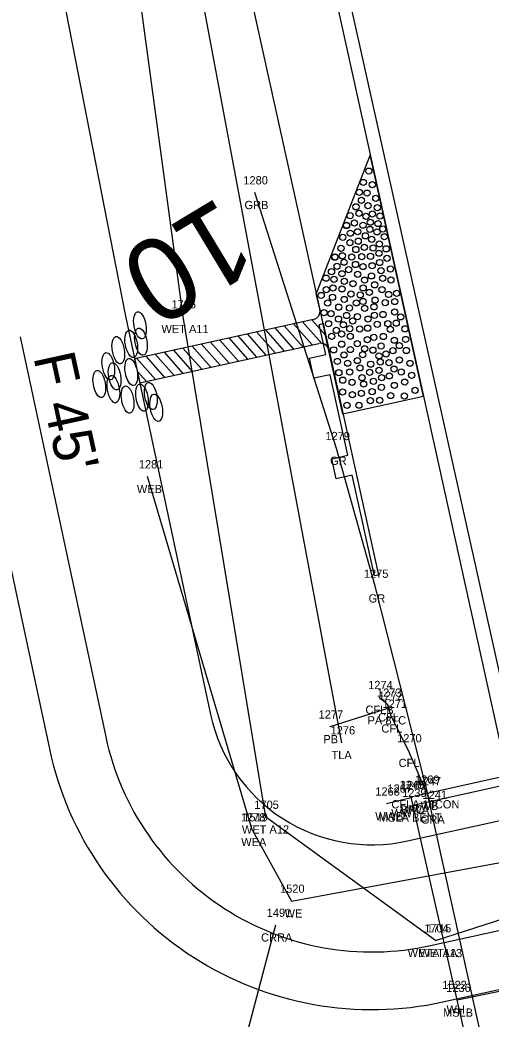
# Model space of a CAD drawing. Extents: x 2521558 to 2525396, y 882711 to 887632.
# Drawn here: x 2523710.8 to 2523767.9, y 885124.5 to 885245.8 of the extents above; entities that cross this region are included whole.
import ezdxf

# ---------------------------------------------------------------- set-up
doc = ezdxf.new("R2010")
doc.units = 0
for name, color, linetype in [('RD_EV_JurisArea', 7, 'Continuous'), ('RD_EX_BldgApp', 7, 'Continuous'), ('RD_EX_BldgApp_txCode', 7, 'Continuous'), ('RD_EX_Bridge', 7, 'Continuous'), ('RD_EX_Bridge_txCode', 7, 'Continuous'), ('RD_EX_Conc', 7, 'Continuous'), ('RD_EX_Conc_txCode', 7, 'Continuous'), ('RD_EX_DR_Pipe', 7, 'Continuous'), ('RD_EX_DR_Pipe_txCode', 7, 'Continuous'), ('RD_EX_GuardRail', 7, 'Continuous'), ('RD_EX_GuardRail_txCode', 7, 'Continuous'), ('RD_EX_H2O', 7, 'Continuous'), ('RD_EX_H2O_txCode', 7, 'Continuous'), ('RD_EX_H2O_WetLd_txCode', 7, 'Continuous'), ('RD_EX_Misc', 7, 'Continuous'), ('RD_EX_Misc_txCode', 7, 'Continuous'), ('RD_EX_Road', 7, 'Continuous'), ('RD_EX_VEG', 7, 'Continuous'), ('RD_EX_VEG_txCode', 7, 'Continuous'), ('RD_HC_TX_Sta50', 7, 'Continuous'), ('RD_PD_BCA', 7, 'Continuous'), ('RD_PD_Bridge', 7, 'Continuous'), ('RD_PD_CstnLmt', 7, 'Continuous'), ('RD_PD_DR_ErosCtrl', 7, 'Continuous'), ('RD_PD_Final_TrvlWay', 7, 'Continuous'), ('RD_PD_GR', 7, 'Continuous'), ('RD_PD_PaveShd', 7, 'Continuous'), ('RD_SMD_Locator', 7, 'Continuous')]:
    doc.layers.add(name, color=color, linetype=linetype)

# ---------------------------------------------------------------- blocks, each defined once
blk = doc.blocks.new('TBC1')
at = {"layer": 'RD_PD_GR'}
blk.add_lwpolyline([(12.5, 2.5), (15, 2.5), (15, 0.49), (25, 0.49), (25, 2.5), (27.5, 2.5), (27.5, 0.49), (31.25, 0.49), (31.25, 0), (0, 0), (0, 0.49), (12.5, 0.49)], close=True, dxfattribs=at)

msp = doc.modelspace()

# ---------------------------------------------------------------- linework, layer by layer
at = {"layer": 'RD_EV_JurisArea'}
for points in [[(2523761.17, 885134.03), (2523740.58, 885149.03), (2523730.55, 885209.77), (2523710.6, 885357.47), (2523698.09, 885411.19), (2523674.93, 885498.62), (2523657.6, 885564.24), (2523640.82, 885610.87), (2523583.66, 885726.91), (2523539.21, 885693.17), (2523494.42, 885646.98)], [(2523761.17, 885134.03), (2523808.21, 885149.21), (2523821.91, 885178.64), (2523802.85, 885236.55), (2523777.81, 885305.56), (2523748.2, 885444.32), (2523730.68, 885516.88), (2523708.64, 885617.3), (2523698.71, 885662.02), (2523727.83, 885665.82), (2523757.3, 885671.75)]]:
    msp.add_lwpolyline(points, dxfattribs=at)
at = {"layer": 'RD_EX_BldgApp'}
msp.add_lwpolyline([(2523776.68, 885077.92), (2523768.27, 885115.31), (2523760.2, 885151.9)], dxfattribs=at)
at = {"layer": 'RD_EX_Bridge'}
for points in [[(2523774.91, 885077.6), (2523821.2, 885087.83), (2523805.06, 885161.89), (2523758.15, 885151.44), (2523774.91, 885077.6)], [(2523758.38, 885151.39), (2523756.7, 885150.99), (2523755.23, 885150.64)]]:
    msp.add_lwpolyline(points, dxfattribs=at)
at = {"layer": 'RD_EX_Conc'}
msp.add_lwpolyline([(2523760.04, 885152.08), (2523757.9, 885157.1), (2523755.8, 885161.28), (2523755.4, 885162.64), (2523754.34, 885163.56)], dxfattribs=at)
at = {"layer": 'RD_EX_DR_Pipe'}
msp.add_line((2523755.61, 885162.27), (2523748.33, 885159.99), dxfattribs=at)
at = {"layer": 'RD_EX_GuardRail'}
for p, q in [((2523749.16, 885193.78), (2523739.25, 885224.82)), ((2523753.83, 885177.07), (2523749.16, 885193.78)), ((2523760.65, 885150.24), (2523753.83, 885177.07))]:
    msp.add_line(p, q, dxfattribs=at)
at = {"layer": 'RD_EX_H2O'}
msp.add_line((2523738.91, 885147.5), (2523726.24, 885190.35), dxfattribs=at)
for points in [[(2523738.91, 885147.5), (2523743.69, 885138.84), (2523816.36, 885152.29), (2523822.43, 885163.3), (2523826.93, 885206.61)], [(2523741.75, 885135.92), (2523732.18, 885099.57), (2523664.9, 885060.26), (2523614.86, 885022.02), (2523558.95, 884972.63), (2523560.62, 884942.42), (2523490.01, 884911.76)]]:
    msp.add_lwpolyline(points, dxfattribs=at)
at = {"layer": 'RD_EX_Misc'}
for p, q in [((2523758.45, 885150.47), (2523805.66, 885161.06)), ((2523810.71, 885136.57), (2523763.83, 885126.8))]:
    msp.add_line(p, q, dxfattribs=at)
at = {"layer": 'RD_EX_Road'}
msp.add_line((2523771.58, 885154.56), (2523750.32, 885250.18), dxfattribs=at)
at = {"layer": 'RD_EX_VEG'}
msp.add_lwpolyline([(2523749.81, 885158.06), (2523732.86, 885248.57), (2523691.62, 885438.95), (2523639.52, 885601.04)], dxfattribs=at)
at = {"layer": 'RD_PD_BCA'}
msp.add_line((2523703.95, 885205.86), (2523714.34, 885157.3), dxfattribs=at)
msp.add_lwpolyline([(2523762.05, 885126.6), (2523810.84, 885137.34)], dxfattribs=at)
msp.add_arc((2523753.45, 885165.66), 40, 192.0677, 282.4185, dxfattribs=at)
at = {"layer": 'RD_PD_CstnLmt'}
for p, q in [((2523704.35, 885308.21), (2523723.51, 885210.04)), ((2523723.51, 885210.04), (2523733.89, 885161.48))]:
    msp.add_line(p, q, dxfattribs=at)
msp.add_lwpolyline([(2523757.75, 885146.13), (2523806.54, 885156.87)], dxfattribs=at)
msp.add_arc((2523753.45, 885165.66), 20, 192.0677, 282.4185, dxfattribs=at)
at = {"layer": 'RD_PD_DR_ErosCtrl'}
msp.add_line((2523710.8, 885207.32), (2523721.18, 885158.76), dxfattribs=at)
msp.add_lwpolyline([(2523760.55, 885133.43), (2523809.33, 885144.17)], dxfattribs=at)
msp.add_arc((2523753.45, 885165.66), 33, 192.0677, 282.4185, dxfattribs=at)
at = {"layer": 'RD_PD_Final_TrvlWay'}
msp.add_line((2523696.8, 885485.75), (2524014, 884045.26), dxfattribs=at)
at = {"layer": 'RD_PD_GR'}
msp.add_line((2523747.52, 885208.93), (2523699.13, 885428.66), dxfattribs=at)
at = {"layer": 'RD_PD_PaveShd'}
for p, q in [((2523753.25, 885229.39), (2523746.71, 885212.59)), ((2523759.7, 885200.09), (2523753.25, 885229.39)), ((2523747.36, 885209.66), (2523746.71, 885212.59)), ((2523746.38, 885209.44), (2523724.66, 885204.65)), ((2523747.37, 885206.53), (2523745.05, 885209.15)), ((2523747.82, 885207.53), (2523746.17, 885209.4)), ((2523748, 885206.73), (2523747.36, 885209.66)), ((2523741.74, 885205.35), (2523739.47, 885207.92)), ((2523742.86, 885205.6), (2523740.59, 885208.17)), ((2523743.98, 885205.84), (2523741.7, 885208.41)), ((2523745.09, 885206.09), (2523742.82, 885208.66)), ((2523746.21, 885206.34), (2523743.94, 885208.91)), ((2523736.16, 885204.12), (2523733.88, 885206.69)), ((2523737.27, 885204.36), (2523735, 885206.93)), ((2523738.39, 885204.61), (2523736.12, 885207.18)), ((2523739.51, 885204.86), (2523737.23, 885207.43)), ((2523740.63, 885205.1), (2523738.35, 885207.67)), ((2523748, 885206.73), (2523749.94, 885197.94)), ((2523749.94, 885197.94), (2523748, 885206.73)), ((2523725.29, 885201.72), (2523747.02, 885206.51)), ((2523730.57, 885202.88), (2523728.3, 885205.45)), ((2523731.69, 885203.13), (2523729.42, 885205.7)), ((2523732.81, 885203.38), (2523730.53, 885205.95)), ((2523733.92, 885203.62), (2523731.65, 885206.19)), ((2523735.04, 885203.87), (2523732.77, 885206.44)), ((2523724.66, 885204.65), (2523725.29, 885201.72)), ((2523727.22, 885202.14), (2523724.95, 885204.71)), ((2523728.34, 885202.39), (2523726.06, 885204.96)), ((2523729.46, 885202.64), (2523727.18, 885205.21)), ((2523726.1, 885201.9), (2523724.98, 885203.17)), ((2523759.7, 885200.09), (2523749.94, 885197.94))]:
    msp.add_line(p, q, dxfattribs=at)
for centre in [(2523753.08, 885227.43), (2523753.08, 885227.43), (2523752.41, 885226.06), (2523752.41, 885226.06), (2523753.51, 885225.78), (2523753.51, 885225.78), (2523751.93, 885224.85), (2523751.93, 885224.85), (2523752.87, 885224.76), (2523752.87, 885224.76), (2523752.18, 885223.88), (2523752.18, 885223.88), (2523752.97, 885223.25), (2523752.97, 885223.25), (2523753.92, 885224.14), (2523753.92, 885224.14), (2523750.81, 885222.03), (2523750.81, 885222.03), (2523751.52, 885223.1), (2523751.89, 885222.31), (2523751.89, 885222.31), (2523753.5, 885222.22), (2523753.5, 885222.22), (2523754.11, 885222.99), (2523754.11, 885222.99), (2523754.42, 885221.99), (2523754.42, 885221.99), (2523750.37, 885220.83), (2523750.38, 885220.87), (2523751.33, 885221.14), (2523751.33, 885221.14), (2523752.36, 885220.87), (2523752.36, 885220.87), (2523752.73, 885221.95), (2523752.73, 885221.95), (2523753.25, 885221.23), (2523753.25, 885221.23), (2523754.19, 885221.07), (2523754.19, 885221.07), (2523750.84, 885219.9), (2523750.84, 885219.9), (2523751.73, 885220.07), (2523751.73, 885220.07), (2523752.67, 885219.58), (2523752.67, 885219.58), (2523753.2, 885220.35), (2523753.2, 885220.35), (2523754.06, 885220.06), (2523754.06, 885220.06), (2523754.77, 885220.41), (2523754.77, 885220.41), (2523749.92, 885219.4), (2523749.92, 885219.4), (2523750.78, 885218.75), (2523750.78, 885218.75), (2523751.79, 885218.93), (2523751.79, 885218.93), (2523753.43, 885219.15), (2523753.43, 885219.15), (2523754.34, 885218.6), (2523754.34, 885218.6), (2523754.95, 885219.46), (2523754.95, 885219.46), (2523749.7, 885218.06), (2523749.7, 885218.06), (2523749.87, 885217.15), (2523749.87, 885217.15), (2523751.5, 885217.92), (2523751.5, 885217.92), (2523752.53, 885218.18), (2523752.53, 885218.18), (2523753.6, 885218.1), (2523753.6, 885218.1), (2523754.3, 885217.47), (2523754.3, 885217.47), (2523755.18, 885218), (2523755.18, 885218), (2523748.95, 885216.99), (2523748.96, 885217), (2523750.08, 885216.38), (2523750.08, 885216.38), (2523751.01, 885217), (2523751.01, 885217), (2523751.46, 885216.1), (2523751.46, 885216.1), (2523752.22, 885217.06), (2523752.22, 885217.06), (2523753.28, 885217.1), (2523753.28, 885217.1), (2523753.48, 885215.94), (2523753.48, 885215.94), (2523754.38, 885216.34), (2523754.38, 885216.34), (2523755.27, 885216.85), (2523755.27, 885216.85), (2523748.55, 885215.24), (2523748.55, 885215.24), (2523749.23, 885215.87), (2523749.23, 885215.87), (2523749.82, 885214.97), (2523749.82, 885214.97), (2523750.64, 885215.48), (2523750.64, 885215.48), (2523751.73, 885214.91), (2523751.73, 885214.91), (2523752.37, 885215.85), (2523752.37, 885215.85), (2523753.4, 885214.72), (2523753.4, 885214.72), (2523754.56, 885215.35), (2523754.56, 885215.35), (2523755.7, 885215.56), (2523755.7, 885215.56), (2523747.88, 885214.44), (2523747.88, 885214.44), (2523748.85, 885214.3), (2523748.85, 885214.3), (2523750.1, 885214.05), (2523750.1, 885214.05), (2523751.15, 885213.76), (2523751.15, 885213.76), (2523752.56, 885214.2), (2523752.56, 885214.2), (2523753.78, 885213.63), (2523753.78, 885213.63), (2523754.76, 885214.43), (2523754.76, 885214.43), (2523755.75, 885214.21), (2523755.75, 885214.21), (2523747.3, 885212.34), (2523747.3, 885212.34), (2523747.3, 885212.34), (2523747.91, 885213.04), (2523747.91, 885213.04), (2523748.73, 885213.24), (2523748.73, 885213.24), (2523749.82, 885213.14), (2523749.82, 885213.14), (2523750.91, 885212.52), (2523750.91, 885212.52), (2523752.03, 885212.41), (2523752.03, 885212.41), (2523752.39, 885213.26), (2523752.39, 885213.26), (2523753.14, 885212.71), (2523753.14, 885212.71), (2523754.68, 885213.04), (2523754.68, 885213.04), (2523755.48, 885212.46), (2523755.48, 885212.46), (2523756.44, 885212.6), (2523756.44, 885212.6), (2523748.09, 885211.43), (2523748.09, 885211.43), (2523748.67, 885212.12), (2523748.67, 885212.12), (2523750.09, 885211.86), (2523750.09, 885211.86), (2523751.57, 885211.44), (2523751.57, 885211.44), (2523752.37, 885211.61), (2523752.37, 885211.61), (2523753.84, 885211.77), (2523753.84, 885211.77), (2523755.06, 885211.47), (2523755.06, 885211.47), (2523756.21, 885211.6), (2523756.21, 885211.6), (2523747.64, 885210.26), (2523747.64, 885210.26), (2523748.49, 885210.14), (2523748.49, 885210.14), (2523749.43, 885210.92), (2523749.43, 885210.92), (2523750.38, 885209.91), (2523750.38, 885209.91), (2523750.73, 885210.81), (2523750.73, 885210.81), (2523752.58, 885210.78), (2523752.58, 885210.78), (2523753.71, 885210.96), (2523753.71, 885210.96), (2523753.76, 885209.93), (2523753.76, 885209.93), (2523754.8, 885210.03), (2523754.8, 885210.03), (2523756.2, 885210.33), (2523756.2, 885210.33), (2523748.19, 885208.9), (2523748.19, 885208.9), (2523749.4, 885209.47), (2523749.4, 885209.47), (2523749.98, 885208.78), (2523749.98, 885208.78), (2523751.11, 885209.24), (2523751.11, 885209.24), (2523751.7, 885209.77), (2523751.7, 885209.77), (2523752.97, 885209.47), (2523752.97, 885209.47), (2523754.09, 885208.84), (2523754.09, 885208.84), (2523755.38, 885208.92), (2523755.38, 885208.92), (2523756.4, 885208.98), (2523756.4, 885208.98), (2523756.94, 885209.74), (2523749.13, 885208.1), (2523749.13, 885208.1), (2523749.78, 885207.67), (2523749.78, 885207.67), (2523750.77, 885208.31), (2523750.77, 885208.31), (2523751.97, 885208.26), (2523751.97, 885208.26), (2523752.93, 885208.37), (2523752.93, 885208.37), (2523755.68, 885208.23), (2523755.68, 885208.23), (2523757.45, 885208.29), (2523757.45, 885208.29), (2523748.58, 885207.38), (2523748.58, 885207.38), (2523749.78, 885206.43), (2523749.78, 885206.43), (2523750.82, 885207.38), (2523750.82, 885207.38), (2523751.67, 885206.49), (2523751.67, 885206.49), (2523752.9, 885206.97), (2523752.9, 885206.97), (2523753.68, 885207.26), (2523753.68, 885207.26), (2523754.84, 885207.36), (2523754.84, 885207.36), (2523756.16, 885206.91), (2523756.16, 885206.91), (2523756.77, 885206.26), (2523756.77, 885206.26), (2523757.54, 885207), (2523757.54, 885207), (2523748.82, 885205.74), (2523748.82, 885205.74), (2523750.07, 885205.13), (2523750.07, 885205.13), (2523750.84, 885205.78), (2523750.84, 885205.78), (2523752.34, 885205.15), (2523752.34, 885205.15), (2523752.58, 885205.87), (2523752.58, 885205.87), (2523753.57, 885205.7), (2523753.57, 885205.7), (2523754.3, 885205.01), (2523754.3, 885205.01), (2523754.57, 885206.2), (2523754.57, 885206.2), (2523755.16, 885205.23), (2523755.16, 885205.23), (2523755.99, 885205.63), (2523755.99, 885205.63), (2523757.63, 885205.66), (2523757.63, 885205.66), (2523749.26, 885204.33), (2523749.26, 885204.33), (2523750.51, 885204.12), (2523750.51, 885204.12), (2523751.68, 885204.44), (2523751.68, 885204.44), (2523753.31, 885204), (2523753.31, 885204), (2523754.46, 885204.26), (2523755.52, 885204.19), (2523755.52, 885204.19), (2523756.78, 885204.5), (2523756.78, 885204.5), (2523758.07, 885204.09), (2523758.07, 885204.09), (2523749.44, 885202.96), (2523749.44, 885202.96), (2523750.76, 885203.04), (2523750.76, 885203.04), (2523751.99, 885203.55), (2523751.99, 885203.55), (2523753.17, 885203), (2523753.17, 885203), (2523754.32, 885203.25), (2523754.32, 885203.25), (2523755.57, 885202.58), (2523755.57, 885202.58), (2523756.14, 885203.4), (2523756.14, 885203.4), (2523757, 885203.06), (2523757, 885203.06), (2523758.26, 885202.64), (2523758.26, 885202.64), (2523749.92, 885202.06), (2523749.92, 885202.06), (2523751.05, 885201.79), (2523751.05, 885201.79), (2523752.24, 885202.37), (2523752.24, 885202.37), (2523752.44, 885201.58), (2523752.44, 885201.58), (2523753.64, 885201.92), (2523753.64, 885201.92), (2523754.62, 885202.37), (2523754.62, 885202.37), (2523756.17, 885201.42), (2523756.17, 885201.42), (2523757.43, 885201.82), (2523757.43, 885201.82), (2523749.89, 885200.63), (2523749.89, 885200.63), (2523751.08, 885200.3), (2523751.08, 885200.3), (2523752.18, 885200.46), (2523752.18, 885200.46), (2523753.48, 885200.66), (2523753.48, 885200.66), (2523754.61, 885201.18), (2523754.61, 885201.18), (2523755.73, 885200.19), (2523755.73, 885200.19), (2523758.69, 885200.82), (2523758.69, 885200.82), (2523750.43, 885199), (2523750.43, 885199), (2523750.43, 885199), (2523751.87, 885199.02), (2523751.87, 885199.02), (2523753.25, 885199.58), (2523753.25, 885199.58), (2523754.4, 885199.62), (2523754.4, 885199.62), (2523757.38, 885200.14), (2523757.38, 885200.14)]:
    msp.add_circle(centre, 0.375, dxfattribs=at)
for centre, start, end in [((2523746.16, 885210.42), 282.4481, 12.4185), ((2523747.24, 885205.54), 12.4185, 102.4481)]:
    msp.add_arc(centre, 1, start, end, dxfattribs=at)
for centre in [(2523725.32, 885208.71), (2523724.26, 885206.47), (2523724.26, 885206.47), (2523725.44, 885206.73), (2523722.69, 885205.7), (2523722.69, 885205.7), (2523721.48, 885203.75), (2523721.48, 885203.75), (2523722.25, 885202.53), (2523722.25, 885202.53), (2523724.26, 885203.06), (2523724.26, 885203.06), (2523720.39, 885201.6), (2523720.39, 885201.6), (2523722.1, 885200.97), (2523722.1, 885200.97), (2523726.64, 885200.14), (2523726.64, 885200.14), (2523723.82, 885199.71), (2523723.82, 885199.71), (2523725.57, 885199.94), (2523725.57, 885199.94), (2523727.29, 885198.71), (2523727.29, 885198.71)]:
    msp.add_ellipse(centre, major_axis=(-0.29, 1.65), ratio=0.429445, dxfattribs=at)
at = {"layer": 'RD_SMD_Locator'}
for centre in [(2523739.25, 885224.82), (2523732.01, 885210.1), (2523749.16, 885193.78), (2523726.24, 885190.35), (2523753.83, 885177.07), (2523754.34, 885163.56), (2523755.4, 885162.64), (2523755.61, 885162.27), (2523755.8, 885161.28), (2523748.33, 885159.99), (2523749.81, 885158.06), (2523757.9, 885157.1), (2523760.04, 885152.08), (2523756.7, 885150.99), (2523758.15, 885151.44), (2523758.38, 885151.39), (2523760.2, 885151.9), (2523755.23, 885150.64), (2523758.45, 885150.47), (2523760.65, 885150.24), (2523740.58, 885149.03), (2523738.91, 885147.5), (2523738.91, 885147.5), (2523743.69, 885138.84), (2523741.75, 885135.92), (2523761.17, 885134.03), (2523761.17, 885134.03), (2523763.32, 885127.16), (2523763.83, 885126.8)]:
    msp.add_circle(centre, 0.001, dxfattribs=at)

# ---------------------------------------------------------------- block references
at = {"layer": 'RD_PD_Bridge', "rotation": 102.41848259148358}
msp.add_blockref('TBC1', (2523754.24, 885178.41), dxfattribs=at)

# ---------------------------------------------------------------- texts
at = {"layer": 'RD_EX_BldgApp_txCode'}
for s, p in [('1247', (2523758.86, 885152.9)), ('WB', (2523759.36, 885149.9)), ('1522', (2523761.98, 885128.16)), ('WH', (2523762.5, 885125.16))]:
    msp.add_text(s, height=1, dxfattribs=at).set_placement(p)
at = {"layer": 'RD_EX_Bridge_txCode'}
for s, p in [('1245', (2523756.8, 885152.44)), ('1266', (2523756.98, 885152.39)), ('1268', (2523753.86, 885151.64)), ('1267', (2523755.33, 885151.99)), ('WWB', (2523753.85, 885148.64)), ('WW', (2523755.8, 885148.99)), ('WWA', (2523756.98, 885149.39)), ('BRC', (2523756.89, 885149.44))]:
    msp.add_text(s, height=1, dxfattribs=at).set_placement(p)
at = {"layer": 'RD_EX_Conc_txCode'}
for s, p in [('1274', (2523753, 885164.56)), ('1273', (2523754.06, 885163.64)), ('1271', (2523754.74, 885162.28)), ('CFLB', (2523752.67, 885161.56)), ('CFL', (2523754.2, 885160.64)), ('CFL', (2523754.6, 885159.28)), ('1270', (2523756.51, 885158.1)), ('CFL', (2523756.69, 885155.1)), ('1269', (2523758.67, 885153.08)), ('CFLA 18CON', (2523755.81, 885150.08))]:
    msp.add_text(s, height=1, dxfattribs=at).set_placement(p)
at = {"layer": 'RD_EX_DR_Pipe_txCode'}
for s, p in [('1272', (2523754.27, 885163.27)), ('1277', (2523746.99, 885160.99)), ('PA 8TC', (2523752.92, 885160.27)), ('PB', (2523747.56, 885157.99))]:
    msp.add_text(s, height=1, dxfattribs=at).set_placement(p)
at = {"layer": 'RD_EX_GuardRail_txCode'}
for s, p in [('1280', (2523737.86, 885225.82)), ('GRB', (2523738, 885222.82)), ('1279', (2523747.81, 885194.78)), ('GR', (2523748.38, 885191.78)), ('1275', (2523752.48, 885178.07)), ('GR', (2523753.05, 885175.07)), ('1241', (2523759.59, 885151.24)), ('GRA', (2523759.38, 885148.24))]:
    msp.add_text(s, height=1, dxfattribs=at).set_placement(p)
at = {"layer": 'RD_EX_H2O_txCode'}
for s, p in [('1281', (2523725.18, 885191.35)), ('WEB', (2523724.95, 885188.35)), ('1278', (2523737.56, 885148.5)), ('1519', (2523737.85, 885148.5)), ('WEA', (2523737.6, 885145.5)), ('WEA', (2523737.6, 885145.5)), ('1520', (2523742.31, 885139.84)), ('1491', (2523740.69, 885136.92)), ('WE', (2523742.86, 885136.84)), ('CRRA', (2523740.01, 885133.92))]:
    msp.add_text(s, height=1, dxfattribs=at).set_placement(p)
at = {"layer": 'RD_EX_H2O_WetLd_txCode'}
for s, p in [('1706', (2523729.14, 885210.77)), ('WET A11', (2523727.93, 885207.77)), ('1705', (2523739.19, 885150.03)), ('WET A12', (2523737.68, 885147.03)), ('1704', (2523759.78, 885135.03)), ('1715', (2523760.1, 885135.03)), ('WETA A13', (2523757.78, 885132.03)), ('WET1A', (2523759.21, 885132.03))]:
    msp.add_text(s, height=1, dxfattribs=at).set_placement(p)
at = {"layer": 'RD_EX_Misc_txCode'}
for s, p in [('1239', (2523757.11, 885151.47)), ('MSLA BENT', (2523754.3, 885148.47)), ('1236', (2523762.46, 885127.8)), ('MSLB', (2523762.07, 885124.8))]:
    msp.add_text(s, height=1, dxfattribs=at).set_placement(p)
at = {"layer": 'RD_EX_VEG_txCode'}
for s, p in [('1276', (2523748.44, 885159.06)), ('TLA', (2523748.55, 885156.06))]:
    msp.add_text(s, height=1, dxfattribs=at).set_placement(p)
at = {"layer": 'RD_HC_TX_Sta50'}
msp.add_text('10', height=10, rotation=211.1184, dxfattribs=at).set_placement((2523734.97, 885224.45))
at = {"layer": 'RD_PD_CstnLmt'}
msp.add_text("F 45'", height=5, rotation=282.4185, dxfattribs=at).set_placement((2523712.38, 885204.89))

doc.saveas('drawing.dxf')
